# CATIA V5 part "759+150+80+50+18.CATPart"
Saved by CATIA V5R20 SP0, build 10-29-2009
Part number: 759+150+80+50+18
Revision: TUTTO
Definition: NON CONOSCIUTO
Nomenclature: 759+150+80+50+18
Source: Unknown
Bounding box of the stored display mesh (mm): x -75 to 75, y -40 to 40, z 0 to 50
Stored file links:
  C:\Users\Utente\Desktop\IO LAVORO\3D X SITO CF\X 3D SITO CF 27-09-2020\759\759+150+80+50+18.CATPart
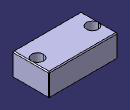
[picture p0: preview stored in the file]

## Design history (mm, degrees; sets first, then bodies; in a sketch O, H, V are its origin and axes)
Body1 "Smusso4" (main body)
  Solid1: solid without history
